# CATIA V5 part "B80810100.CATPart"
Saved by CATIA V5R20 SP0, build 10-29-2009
Part number: B80810100
Revision: 4
Definition: design
Nomenclature: B80810100
Source: made
Description: NOT SPECIFIED
Bounding box of the stored display mesh (mm): x -6.824 to 6.824, y -7 to 7, z 0 to 100
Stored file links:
  C:\Users\Raffaele\Desktop\3D X SITO CF\BOLEX\4-PILLAR REF 808\B80810100.CATPart
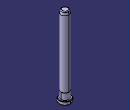
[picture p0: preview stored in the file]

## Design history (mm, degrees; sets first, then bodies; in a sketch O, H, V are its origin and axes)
Body1 "MANIFOLD_SOLID_BREP #450" (main body)
  Solid1: solid without history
